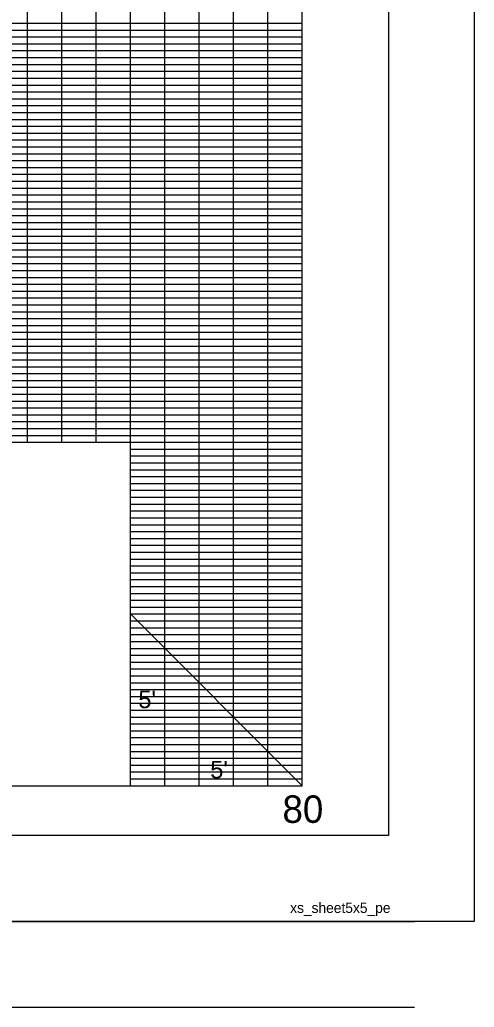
# Model space of a CAD drawing. Extents: x -15 to 165, y -6 to 109.
# Drawn here: x 151.78 to 165.01, y -6.45 to 22.3 of the extents above; entities that cross this region are included whole.
import ezdxf

# ---------------------------------------------------------------- set-up
doc = ezdxf.new("R2010")
doc.units = 0
for name, color, linetype in [('RD_SHT_Bndy', 7, 'Continuous'), ('RD_SHT_Iplotshp', 7, 'Continuous'), ('RD_SHT_MjGrid', 7, 'Continuous'), ('RD_SHT_MnGrid', 7, 'Continuous'), ('RD_SHT_SubGrid', 7, 'Continuous'), ('RD_SHT_TX', 7, 'Continuous')]:
    doc.layers.add(name, color=color, linetype=linetype)

msp = doc.modelspace()

# ---------------------------------------------------------------- linework, layer by layer
at = {"layer": 'RD_SHT_Bndy'}
for p, q in [((155, 5), (160, 0)), ((-12.73, -3.949), (163.27, -3.949)), ((-12.73, -6.449), (163.27, -6.449))]:
    msp.add_line(p, q, dxfattribs=at)
msp.add_lwpolyline([(-4.99, 103.551), (162.51, 103.551), (162.51, -1.449), (-4.99, -1.449)], close=True, dxfattribs=at)
at = {"layer": 'RD_SHT_Iplotshp'}
msp.add_lwpolyline([(-14.589, 106.051), (165.01, 106.051), (165.01, -3.949), (-14.589, -3.949)], close=True, dxfattribs=at)
at = {"layer": 'RD_SHT_MjGrid'}
for p, q in [((155, 0), (155, 100)), ((160, 0), (160, 100)), ((0, 20), (160, 20)), ((0, 15), (160, 15)), ((0, 10), (160, 10)), ((155, 5), (160, 5)), ((0, 0), (160, 0))]:
    msp.add_line(p, q, dxfattribs=at)
at = {"layer": 'RD_SHT_MnGrid'}
for p, q in [((152, 10), (152, 100)), ((153, 10), (153, 100)), ((154, 10), (154, 100)), ((156, 0), (156, 100)), ((157, 0), (157, 100)), ((158, 0), (158, 100)), ((159, 0), (159, 100)), ((0, 22), (160, 22)), ((0, 21), (160, 21)), ((0, 19), (160, 19)), ((0, 18), (160, 18)), ((0, 17), (160, 17)), ((0, 16), (160, 16)), ((0, 14), (160, 14)), ((0, 13), (160, 13)), ((0, 12), (160, 12)), ((0, 11), (160, 11)), ((155, 9), (160, 9)), ((155, 8), (160, 8)), ((155, 7), (160, 7)), ((155, 6), (160, 6)), ((155, 4), (160, 4)), ((155, 3), (160, 3)), ((155, 2), (160, 2)), ((155, 1), (160, 1))]:
    msp.add_line(p, q, dxfattribs=at)
at = {"layer": 'RD_SHT_SubGrid'}
for p, q in [((0, 22.2), (160, 22.2)), ((0, 21.8), (160, 21.8)), ((0, 21.6), (160, 21.6)), ((0, 21.4), (160, 21.4)), ((0, 21.2), (160, 21.2)), ((0, 20.8), (160, 20.8)), ((0, 20.6), (160, 20.6)), ((0, 20.4), (160, 20.4)), ((0, 20.2), (160, 20.2)), ((0, 19.8), (160, 19.8)), ((0, 19.6), (160, 19.6)), ((0, 19.4), (160, 19.4)), ((0, 19.2), (160, 19.2)), ((0, 18.8), (160, 18.8)), ((0, 18.6), (160, 18.6)), ((0, 18.4), (160, 18.4)), ((0, 18.2), (160, 18.2)), ((0, 17.8), (160, 17.8)), ((0, 17.6), (160, 17.6)), ((0, 17.4), (160, 17.4)), ((0, 17.2), (160, 17.2)), ((0, 16.8), (160, 16.8)), ((0, 16.6), (160, 16.6)), ((0, 16.4), (160, 16.4)), ((0, 16.2), (160, 16.2)), ((0, 15.8), (160, 15.8)), ((0, 15.6), (160, 15.6)), ((0, 15.4), (160, 15.4)), ((0, 15.2), (160, 15.2)), ((0, 14.8), (160, 14.8)), ((0, 14.6), (160, 14.6)), ((0, 14.4), (160, 14.4)), ((0, 14.2), (160, 14.2)), ((0, 13.8), (160, 13.8)), ((0, 13.6), (160, 13.6)), ((0, 13.4), (160, 13.4)), ((0, 13.2), (160, 13.2)), ((0, 12.8), (160, 12.8)), ((0, 12.6), (160, 12.6)), ((0, 12.4), (160, 12.4)), ((0, 12.2), (160, 12.2)), ((0, 11.8), (160, 11.8)), ((0, 11.6), (160, 11.6)), ((0, 11.4), (160, 11.4)), ((0, 11.2), (160, 11.2)), ((0, 10.8), (160, 10.8)), ((0, 10.6), (160, 10.6)), ((0, 10.4), (160, 10.4)), ((0, 10.2), (160, 10.2)), ((155, 9.8), (160, 9.8)), ((155, 9.6), (160, 9.6)), ((155, 9.4), (160, 9.4)), ((155, 9.2), (160, 9.2)), ((155, 8.8), (160, 8.8)), ((155, 8.6), (160, 8.6)), ((155, 8.4), (160, 8.4)), ((155, 8.2), (160, 8.2)), ((155, 7.8), (160, 7.8)), ((155, 7.6), (160, 7.6)), ((155, 7.4), (160, 7.4)), ((155, 7.2), (160, 7.2)), ((155, 6.8), (160, 6.8)), ((155, 6.6), (160, 6.6)), ((155, 6.4), (160, 6.4)), ((155, 6.2), (160, 6.2)), ((155, 5.8), (160, 5.8)), ((155, 5.6), (160, 5.6)), ((155, 5.4), (160, 5.4)), ((155, 5.2), (160, 5.2)), ((155, 5), (160, 5)), ((155, 4.8), (160, 4.8)), ((155, 4.6), (160, 4.6)), ((155, 4.4), (160, 4.4)), ((155, 4.2), (160, 4.2)), ((155, 3.8), (160, 3.8)), ((155, 3.6), (160, 3.6)), ((155, 3.4), (160, 3.4)), ((155, 3.2), (160, 3.2)), ((155, 2.8), (160, 2.8)), ((155, 2.6), (160, 2.6)), ((155, 2.4), (160, 2.4)), ((155, 2.2), (160, 2.2)), ((155, 1.8), (160, 1.8)), ((155, 1.6), (160, 1.6)), ((155, 1.4), (160, 1.4)), ((155, 1.2), (160, 1.2)), ((155, 0.8), (160, 0.8)), ((155, 0.6), (160, 0.6)), ((155, 0.4), (160, 0.4)), ((155, 0.2), (160, 0.2))]:
    msp.add_line(p, q, dxfattribs=at)

# ---------------------------------------------------------------- texts
at = {"layer": 'RD_SHT_TX'}
for s, height, p in [("5'", 0.512, (155.231, 2.258)), ("5'", 0.512, (157.325, 0.211)), ('80', 0.8, (159.426, -1.082)), ('xs_sheet5x5_pe', 0.3, (159.65, -3.704))]:
    msp.add_text(s, height=height, dxfattribs=at).set_placement(p)

doc.saveas('drawing.dxf')
